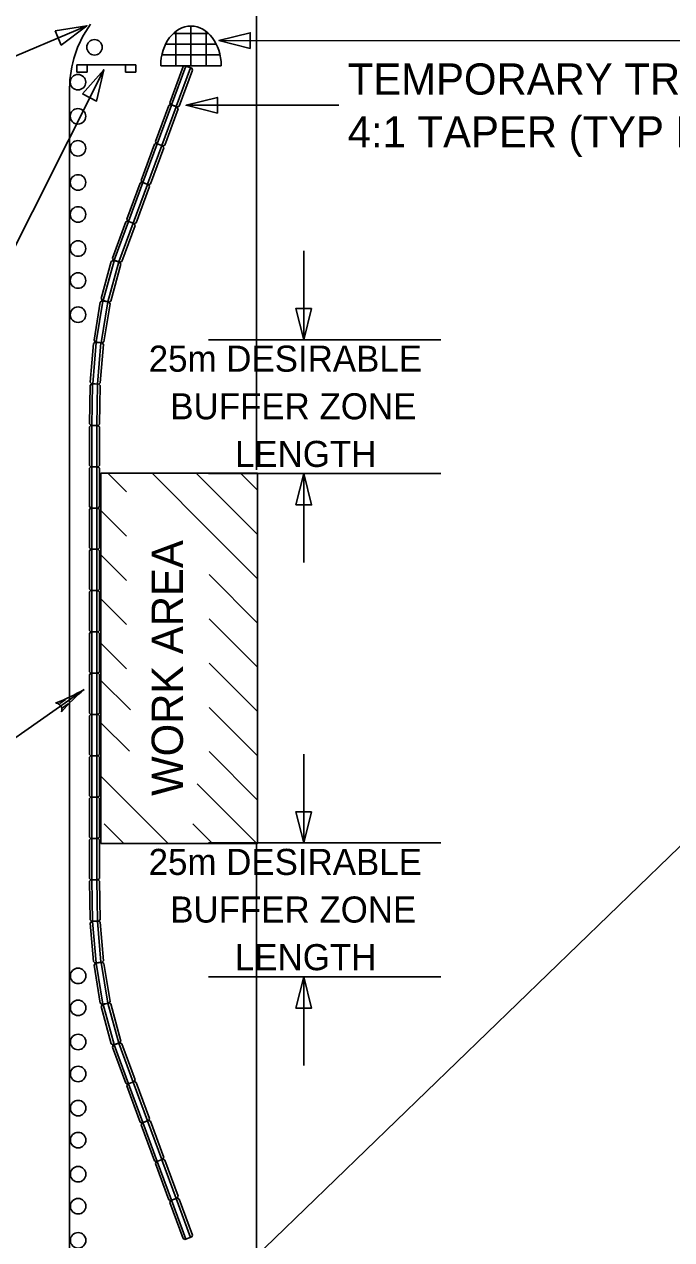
# Model space of a CAD drawing. Extents: x 2179 to 2395, y 134 to 413.
# Drawn here: x 2223.4 to 2253.5, y 308.2 to 364.6 of the extents above; entities that cross this region are included whole.
import ezdxf

# ---------------------------------------------------------------- set-up
doc = ezdxf.new("R2010")
doc.units = 0
for name, color, linetype in [('Level 10', 7, 'Continuous'), ('Level 4', 7, 'Continuous'), ('Level 44', 7, 'Continuous'), ('Level 5', 7, 'Continuous')]:
    doc.layers.add(name, color=color, linetype=linetype)

# ---------------------------------------------------------------- blocks, each defined once
blk = doc.blocks.new('OLDARO')
at = {"layer": 'Level 5'}
for p, q in [((-2.01, 0.25), (-2.69, 0.25)), ((-2.05, -0.25), (-2.73, -0.25))]:
    blk.add_line(p, q, dxfattribs=at)
for centre, radius, start, end in [((-3.37, 0), 0.626, 306.6131, 53.1011), ((1.47, 17.94), 18, 255.6368, 265.3145), ((1.31, -17.1), 17.15, 94.3866, 104.5536)]:
    blk.add_arc(centre, radius, start, end, dxfattribs=at)

msp = doc.modelspace()

# ---------------------------------------------------------------- linework, layer by layer
at = {"layer": 'Level 10'}
for p, q in [((2234.191, 343.931), (2234.191, 399.312)), ((2214.353, 359.476), (2226.333, 364.537)), ((2232.456, 363.851), (2259.582, 363.833)), ((2225.866, 362.728), (2228.601, 362.728)), ((2225.866, 362.728), (2225.866, 362.389)), ((2226.35, 362.728), (2226.35, 362.389)), ((2228.118, 362.728), (2228.118, 362.389)), ((2228.601, 362.728), (2228.601, 362.388)), ((2227.115, 362.499), (2213.674, 335.743)), ((2225.866, 362.389), (2226.35, 362.389)), ((2228.118, 362.388), (2228.601, 362.388)), ((2230.93, 360.851), (2238.022, 360.851)), ((2236.39, 349.972), (2236.39, 354.088)), ((2231.974, 349.972), (2242.752, 349.972)), ((2226.983, 326.608), (2226.983, 343.778)), ((2234.248, 343.778), (2226.983, 343.778)), ((2228.165, 342.912), (2227.299, 343.778)), ((2232.112, 341.018), (2229.352, 343.778)), ((2232.033, 343.149), (2231.404, 343.778)), ((2231.974, 343.759), (2242.752, 343.759)), ((2234.248, 342.988), (2233.458, 343.778)), ((2234.248, 326.608), (2234.248, 343.778)), ((2236.39, 339.644), (2236.39, 343.759)), ((2234.248, 340.935), (2232.003, 343.18)), ((2228.165, 340.86), (2226.989, 342.036)), ((2234.248, 338.882), (2232.003, 341.127)), ((2228.165, 338.807), (2226.989, 339.983)), ((2234.248, 336.83), (2232.003, 339.075)), ((2228.165, 336.754), (2226.989, 337.93)), ((2234.248, 334.777), (2232.003, 337.022)), ((2228.165, 334.701), (2226.989, 335.877)), ((2234.248, 332.725), (2232.003, 334.969)), ((2228.35, 332.8), (2226.949, 334.201)), ((2213.934, 325.161), (2226.209, 333.747)), ((2234.248, 330.672), (2232.003, 332.916)), ((2228.302, 330.884), (2226.983, 332.203)), ((2234.248, 328.619), (2232.003, 330.864)), ((2236.385, 326.627), (2236.385, 330.742)), ((2230.101, 326.608), (2226.983, 329.726)), ((2234.248, 326.567), (2231.447, 329.368)), ((2231.006, 304.399), (2256.495, 329.053)), ((2228.048, 326.608), (2227.138, 327.519)), ((2232.154, 326.608), (2231.241, 327.521)), ((2234.248, 326.608), (2226.983, 326.608)), ((2231.97, 326.627), (2242.747, 326.627)), ((2234.191, 178.244), (2234.191, 326.608)), ((2231.97, 320.414), (2242.747, 320.414)), ((2236.385, 316.298), (2236.385, 320.414)), ((2225.531, 313.635), (2225.531, 306.457))]:
    msp.add_line(p, q, dxfattribs=at)
for points in [[(2233.907, 363.487), (2232.456, 363.851), (2233.907, 364.212)], [(2226.133, 361.371), (2227.115, 362.499), (2226.78, 361.042)], [(2232.381, 360.488), (2230.93, 360.851), (2232.381, 361.213)], [(2236.022, 318.963), (2236.385, 320.414), (2236.748, 318.963)]]:
    msp.add_lwpolyline(points, close=True, dxfattribs=at)
for centre in [(2226.683, 363.538), (2225.918, 361.918), (2225.918, 360.335), (2225.918, 358.851), (2225.919, 357.268), (2225.919, 355.784), (2225.919, 354.2), (2225.919, 352.716), (2225.919, 351.133), (2225.923, 320.461), (2225.923, 318.977), (2225.923, 317.394), (2225.923, 315.91), (2225.924, 314.327), (2225.924, 312.843), (2225.924, 311.26), (2225.924, 309.776), (2225.924, 308.193)]:
    msp.add_circle(centre, 0.359, dxfattribs=at)
at = {"layer": 'Level 4'}
for p, q in [((2230.456, 362.683), (2230.456, 364.278)), ((2231.156, 362.683), (2231.156, 364.525)), ((2231.856, 362.683), (2231.856, 364.278)), ((2229.98, 363.683), (2232.333, 363.683)), ((2230.343, 364.183), (2231.969, 364.183)), ((2229.807, 363.183), (2232.506, 363.183)), ((2229.753, 362.683), (2232.56, 362.683)), ((2230.796, 362.643), (2230.176, 360.966)), ((2230.262, 360.865), (2230.927, 362.664)), ((2230.478, 360.786), (2231.142, 362.585)), ((2230.881, 362.681), (2230.796, 362.643)), ((2231.191, 362.567), (2230.881, 362.681)), ((2231.23, 362.483), (2231.191, 362.567)), ((2230.61, 360.806), (2231.23, 362.483)), ((2229.592, 359.061), (2230.257, 360.86)), ((2230.211, 360.878), (2230.126, 360.839)), ((2230.176, 360.966), (2230.215, 360.882)), ((2230.521, 360.763), (2230.211, 360.878)), ((2230.215, 360.882), (2230.526, 360.768)), ((2230.126, 360.839), (2229.506, 359.162)), ((2229.808, 358.982), (2230.472, 360.782)), ((2229.941, 359.003), (2230.56, 360.679)), ((2230.56, 360.679), (2230.521, 360.763)), ((2230.61, 360.806), (2230.526, 360.768)), ((2229.506, 359.162), (2229.546, 359.078)), ((2229.463, 359.038), (2228.843, 357.361)), ((2228.929, 357.26), (2229.594, 359.059)), ((2229.144, 357.181), (2229.809, 358.981)), ((2229.277, 357.202), (2229.896, 358.878)), ((2229.548, 359.077), (2229.463, 359.038)), ((2229.546, 359.078), (2229.856, 358.964)), ((2229.858, 358.962), (2229.548, 359.077)), ((2229.941, 359.003), (2229.856, 358.964)), ((2229.896, 358.878), (2229.858, 358.962)), ((2228.802, 357.237), (2228.182, 355.56)), ((2228.268, 355.459), (2228.933, 357.258)), ((2228.484, 355.38), (2229.148, 357.18)), ((2228.617, 355.401), (2229.236, 357.077)), ((2228.888, 357.276), (2228.802, 357.237)), ((2228.843, 357.361), (2228.882, 357.277)), ((2228.882, 357.277), (2229.193, 357.163)), ((2229.197, 357.161), (2228.888, 357.276)), ((2229.277, 357.202), (2229.193, 357.163)), ((2229.236, 357.077), (2229.197, 357.161)), ((2228.135, 355.438), (2227.515, 353.761)), ((2227.601, 353.66), (2228.266, 355.459)), ((2227.816, 353.581), (2228.481, 355.381)), ((2227.949, 353.602), (2228.569, 355.278)), ((2228.22, 355.477), (2228.135, 355.438)), ((2228.182, 355.56), (2228.222, 355.477)), ((2228.53, 355.362), (2228.22, 355.477)), ((2228.222, 355.477), (2228.532, 355.362)), ((2228.569, 355.278), (2228.53, 355.362)), ((2228.617, 355.401), (2228.532, 355.362)), ((2227.463, 353.604), (2226.993, 351.879)), ((2227.087, 351.786), (2227.592, 353.637)), ((2227.309, 351.726), (2227.813, 353.578)), ((2227.545, 353.65), (2227.463, 353.604)), ((2227.515, 353.761), (2227.554, 353.678)), ((2227.864, 353.563), (2227.545, 353.65)), ((2227.554, 353.678), (2227.865, 353.563)), ((2227.909, 353.483), (2227.864, 353.563)), ((2227.949, 353.602), (2227.865, 353.563)), ((2227.44, 351.759), (2227.909, 353.483)), ((2226.993, 351.879), (2227.04, 351.799)), ((2226.954, 351.715), (2226.662, 349.952)), ((2226.766, 349.868), (2227.078, 351.761)), ((2227.03, 351.769), (2226.954, 351.715)), ((2226.992, 349.831), (2227.305, 351.725)), ((2227.356, 351.715), (2227.03, 351.769)), ((2227.04, 351.799), (2227.359, 351.713)), ((2227.119, 349.877), (2227.41, 351.64)), ((2227.41, 351.64), (2227.356, 351.715)), ((2227.44, 351.759), (2227.359, 351.713)), ((2226.635, 349.789), (2226.49, 348.007)), ((2226.599, 347.933), (2226.756, 349.844)), ((2226.707, 349.849), (2226.635, 349.789)), ((2226.662, 349.952), (2226.717, 349.877)), ((2227.037, 349.821), (2226.707, 349.849)), ((2226.717, 349.877), (2227.044, 349.823)), ((2226.828, 347.913), (2226.985, 349.826)), ((2226.951, 347.969), (2227.096, 349.751)), ((2227.096, 349.751), (2227.037, 349.821)), ((2227.119, 349.877), (2227.044, 349.823)), ((2226.549, 347.918), (2226.483, 347.854)), ((2226.49, 348.007), (2226.549, 347.937)), ((2226.549, 347.937), (2226.879, 347.91)), ((2226.88, 347.912), (2226.549, 347.918)), ((2226.567, 346), (2226.598, 347.917)), ((2226.796, 345.995), (2226.829, 347.914)), ((2226.951, 347.969), (2226.879, 347.91)), ((2226.945, 347.846), (2226.88, 347.912)), ((2226.483, 347.854), (2226.452, 346.067)), ((2226.914, 346.058), (2226.945, 347.846)), ((2226.515, 345.996), (2226.449, 345.931)), ((2226.449, 345.931), (2226.451, 344.143)), ((2226.452, 346.067), (2226.517, 346.001)), ((2226.846, 345.996), (2226.515, 345.996)), ((2226.517, 346.001), (2226.847, 345.995)), ((2226.566, 344.078), (2226.564, 345.995)), ((2226.796, 344.077), (2226.794, 345.997)), ((2226.911, 345.931), (2226.846, 345.996)), ((2226.914, 346.058), (2226.847, 345.995)), ((2226.913, 344.143), (2226.911, 345.931)), ((2226.515, 344.081), (2226.449, 344.016)), ((2226.449, 344.016), (2226.451, 342.228)), ((2226.451, 344.143), (2226.517, 344.078)), ((2226.846, 344.08), (2226.515, 344.081)), ((2226.517, 344.078), (2226.847, 344.078)), ((2226.566, 342.163), (2226.564, 344.08)), ((2226.796, 342.162), (2226.794, 344.082)), ((2226.911, 344.016), (2226.846, 344.08)), ((2226.913, 344.143), (2226.847, 344.078)), ((2226.913, 342.228), (2226.911, 344.016)), ((2226.515, 342.166), (2226.449, 342.1)), ((2226.449, 342.1), (2226.451, 340.313)), ((2226.451, 342.228), (2226.517, 342.163)), ((2226.846, 342.165), (2226.515, 342.166)), ((2226.517, 342.163), (2226.847, 342.163)), ((2226.566, 340.248), (2226.564, 342.165)), ((2226.796, 340.247), (2226.794, 342.166)), ((2226.911, 342.101), (2226.846, 342.165)), ((2226.913, 342.228), (2226.847, 342.163)), ((2226.913, 340.313), (2226.911, 342.101)), ((2226.515, 340.251), (2226.449, 340.185)), ((2226.449, 340.185), (2226.451, 338.398)), ((2226.451, 340.313), (2226.517, 340.248)), ((2226.846, 340.25), (2226.515, 340.251)), ((2226.517, 340.248), (2226.847, 340.248)), ((2226.566, 338.333), (2226.564, 340.25)), ((2226.796, 338.332), (2226.794, 340.251)), ((2226.911, 340.186), (2226.846, 340.25)), ((2226.913, 340.313), (2226.847, 340.248)), ((2226.913, 338.398), (2226.911, 340.186)), ((2226.515, 338.336), (2226.449, 338.27)), ((2226.451, 338.398), (2226.517, 338.333)), ((2226.846, 338.335), (2226.515, 338.336)), ((2226.517, 338.333), (2226.847, 338.333)), ((2226.566, 336.418), (2226.564, 338.335)), ((2226.796, 336.417), (2226.794, 338.336)), ((2226.911, 338.271), (2226.846, 338.335)), ((2226.913, 338.398), (2226.847, 338.333)), ((2226.449, 338.27), (2226.451, 336.483)), ((2226.913, 336.483), (2226.911, 338.271)), ((2226.449, 334.561), (2226.45, 336.349)), ((2226.45, 336.349), (2226.516, 336.414)), ((2226.451, 336.483), (2226.517, 336.418)), ((2226.516, 336.414), (2226.847, 336.413)), ((2226.517, 336.418), (2226.847, 336.418)), ((2226.566, 336.414), (2226.563, 334.496)), ((2226.795, 336.414), (2226.794, 334.495)), ((2226.913, 336.483), (2226.847, 336.418)), ((2226.913, 336.349), (2226.847, 336.413)), ((2226.913, 336.349), (2226.911, 334.56)), ((2226.514, 334.496), (2226.449, 334.561)), ((2226.449, 332.646), (2226.45, 334.433)), ((2226.45, 334.433), (2226.516, 334.498)), ((2226.845, 334.496), (2226.514, 334.496)), ((2226.516, 334.498), (2226.847, 334.498)), ((2226.566, 334.498), (2226.563, 332.581)), ((2226.795, 334.499), (2226.794, 332.58)), ((2226.911, 334.56), (2226.845, 334.496)), ((2226.913, 334.434), (2226.847, 334.498)), ((2226.913, 334.434), (2226.911, 332.645)), ((2226.514, 332.58), (2226.449, 332.646)), ((2226.449, 330.731), (2226.45, 332.518)), ((2226.45, 332.518), (2226.516, 332.583)), ((2226.845, 332.581), (2226.514, 332.58)), ((2226.516, 332.583), (2226.847, 332.583)), ((2226.566, 332.583), (2226.563, 330.666)), ((2226.795, 332.584), (2226.794, 330.665)), ((2226.911, 332.645), (2226.845, 332.581)), ((2226.913, 332.518), (2226.847, 332.583)), ((2226.913, 332.518), (2226.911, 330.73)), ((2226.514, 330.665), (2226.449, 330.731)), ((2226.449, 328.816), (2226.45, 330.603)), ((2226.45, 330.603), (2226.516, 330.668)), ((2226.845, 330.666), (2226.514, 330.665)), ((2226.516, 330.668), (2226.847, 330.668)), ((2226.566, 330.668), (2226.563, 328.751)), ((2226.795, 330.669), (2226.794, 328.75)), ((2226.911, 330.73), (2226.845, 330.666)), ((2226.913, 330.603), (2226.847, 330.668)), ((2226.913, 330.603), (2226.911, 328.815)), ((2226.514, 328.75), (2226.449, 328.816)), ((2226.45, 328.688), (2226.516, 328.753)), ((2226.845, 328.751), (2226.514, 328.75)), ((2226.516, 328.753), (2226.847, 328.753)), ((2226.566, 328.753), (2226.563, 326.836)), ((2226.795, 328.754), (2226.794, 326.835)), ((2226.911, 328.815), (2226.845, 328.751)), ((2226.913, 328.688), (2226.847, 328.753)), ((2226.449, 326.901), (2226.45, 328.688)), ((2226.913, 328.688), (2226.911, 326.9)), ((2226.514, 326.835), (2226.449, 326.901)), ((2226.449, 324.985), (2226.45, 326.773)), ((2226.45, 326.773), (2226.516, 326.838)), ((2226.845, 326.836), (2226.514, 326.835)), ((2226.516, 326.838), (2226.847, 326.838)), ((2226.566, 326.838), (2226.563, 324.921)), ((2226.795, 326.839), (2226.794, 324.919)), ((2226.911, 326.9), (2226.845, 326.836)), ((2226.913, 326.773), (2226.847, 326.838)), ((2226.913, 326.773), (2226.911, 324.985)), ((2226.514, 324.92), (2226.449, 324.985)), ((2226.451, 324.849), (2226.516, 324.915)), ((2226.482, 323.062), (2226.451, 324.849)), ((2226.845, 324.921), (2226.514, 324.92)), ((2226.516, 324.915), (2226.847, 324.921)), ((2226.566, 324.916), (2226.598, 322.999)), ((2226.795, 324.921), (2226.828, 323.002)), ((2226.911, 324.985), (2226.845, 324.921)), ((2226.914, 324.858), (2226.847, 324.921)), ((2226.914, 324.858), (2226.944, 323.07)), ((2226.944, 323.07), (2226.88, 323.004)), ((2226.549, 322.998), (2226.482, 323.062)), ((2226.489, 322.909), (2226.549, 322.979)), ((2226.635, 321.128), (2226.489, 322.909)), ((2226.549, 322.979), (2226.879, 323.006)), ((2226.88, 323.004), (2226.549, 322.998)), ((2226.598, 322.983), (2226.755, 321.072)), ((2226.828, 323.003), (2226.984, 321.09)), ((2226.95, 322.947), (2226.879, 323.006)), ((2226.95, 322.947), (2227.096, 321.165)), ((2226.707, 321.067), (2226.635, 321.128)), ((2226.662, 320.965), (2226.716, 321.04)), ((2226.953, 319.201), (2226.662, 320.965)), ((2227.036, 321.095), (2226.707, 321.067)), ((2226.716, 321.04), (2227.043, 321.093)), ((2226.765, 321.048), (2227.078, 319.155)), ((2226.992, 321.085), (2227.304, 319.191)), ((2227.096, 321.165), (2227.036, 321.095)), ((2227.118, 321.039), (2227.043, 321.093)), ((2227.118, 321.039), (2227.409, 319.276)), ((2227.03, 319.147), (2226.953, 319.201)), ((2227.356, 319.201), (2227.03, 319.147)), ((2227.039, 319.117), (2227.359, 319.203)), ((2227.087, 319.13), (2227.591, 317.279)), ((2227.309, 319.19), (2227.813, 317.338)), ((2227.409, 319.276), (2227.356, 319.201)), ((2227.439, 319.158), (2227.359, 319.203)), ((2227.439, 319.158), (2227.909, 317.433)), ((2226.992, 319.037), (2227.039, 319.117)), ((2227.463, 317.312), (2226.992, 319.037)), ((2227.909, 317.433), (2227.863, 317.353)), ((2227.544, 317.266), (2227.463, 317.312)), ((2227.514, 317.155), (2227.554, 317.239)), ((2228.134, 315.478), (2227.514, 317.155)), ((2227.863, 317.353), (2227.544, 317.266)), ((2227.554, 317.239), (2227.865, 317.353)), ((2227.6, 317.256), (2228.265, 315.457)), ((2227.816, 317.335), (2228.481, 315.535)), ((2227.949, 317.314), (2227.865, 317.353)), ((2227.949, 317.314), (2228.568, 315.638)), ((2228.22, 315.439), (2228.134, 315.478)), ((2228.182, 315.356), (2228.221, 315.44)), ((2228.802, 313.679), (2228.182, 315.356)), ((2228.53, 315.554), (2228.22, 315.439)), ((2228.221, 315.44), (2228.532, 315.554)), ((2228.268, 315.457), (2228.933, 313.658)), ((2228.483, 315.536), (2229.148, 313.736)), ((2228.568, 315.638), (2228.53, 315.554)), ((2228.616, 315.515), (2228.532, 315.554)), ((2228.616, 315.515), (2229.235, 313.839)), ((2228.887, 313.64), (2228.802, 313.679)), ((2228.842, 313.555), (2228.882, 313.639)), ((2229.462, 311.878), (2228.842, 313.555)), ((2228.882, 313.639), (2229.193, 313.753)), ((2229.197, 313.755), (2228.887, 313.64)), ((2228.928, 313.656), (2229.593, 311.857)), ((2229.144, 313.735), (2229.809, 311.935)), ((2229.277, 313.714), (2229.193, 313.753)), ((2229.235, 313.839), (2229.197, 313.755)), ((2229.277, 313.714), (2229.896, 312.038)), ((2229.548, 311.839), (2229.462, 311.878)), ((2229.506, 311.754), (2229.545, 311.838)), ((2229.545, 311.838), (2229.856, 311.952)), ((2229.857, 311.954), (2229.548, 311.839)), ((2229.592, 311.855), (2230.257, 310.056)), ((2229.807, 311.934), (2230.472, 310.134)), ((2229.94, 311.913), (2229.856, 311.952)), ((2229.896, 312.038), (2229.857, 311.954)), ((2229.94, 311.913), (2230.559, 310.237)), ((2230.126, 310.077), (2229.506, 311.754)), ((2230.521, 310.153), (2230.211, 310.038)), ((2230.215, 310.034), (2230.526, 310.148)), ((2230.477, 310.131), (2231.142, 308.331)), ((2230.559, 310.237), (2230.521, 310.153)), ((2230.61, 310.11), (2230.526, 310.148)), ((2230.61, 310.11), (2231.229, 308.433)), ((2230.211, 310.038), (2230.126, 310.077)), ((2230.175, 309.95), (2230.215, 310.034)), ((2230.796, 308.274), (2230.175, 309.95)), ((2230.261, 310.051), (2230.926, 308.252)), ((2231.229, 308.433), (2231.191, 308.349)), ((2230.881, 308.235), (2230.796, 308.274)), ((2231.191, 308.349), (2230.881, 308.235))]:
    msp.add_line(p, q, dxfattribs=at)
msp.add_ellipse((2231.156, 362.675), major_axis=(0, 1.85), ratio=0.758621, start_param=4.716532, end_param=7.849839, dxfattribs=at)
at = {"layer": 'Level 5'}
msp.add_line((2225.531, 313.635), (2225.531, 361.641), dxfattribs=at)
for points in [[(2224.855, 364.306), (2226.333, 364.537), (2225.138, 363.638)], [(2236.753, 351.423), (2236.39, 349.972), (2236.027, 351.423)], [(2236.027, 342.308), (2236.39, 343.759), (2236.753, 342.308)], [(2236.748, 328.078), (2236.385, 326.627), (2236.023, 328.078)]]:
    msp.add_lwpolyline(points, close=True, dxfattribs=at)
msp.add_arc((2230.531, 361.641), 5, 143.6679, 180, dxfattribs=at)

# ---------------------------------------------------------------- block references
at = {"layer": 'Level 10', "xscale": 0.4838, "yscale": 0.4838000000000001, "rotation": 34.97582831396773}
msp.add_blockref('OLDARO', (2226.209, 333.747), dxfattribs=at)

# ---------------------------------------------------------------- texts
at = {"layer": 'Level 10'}
for s, p in [('TEMPORARY TRAFFIC BARRIER ', (2238.429, 361.34)), ('4:1 TAPER (TYP BOTH ENDS)', (2238.429, 358.889))]:
    msp.add_text(s, height=1.451, dxfattribs=at).set_placement(p)
msp.add_text('WORK AREA', height=1.4514, rotation=90, dxfattribs=at).set_placement((2230.785, 328.812))
at = {"layer": 'Level 44'}
for s, p in [('25m DESIRABLE', (2229.199, 348.489)), ('BUFFER ZONE', (2230.199, 346.279)), ('LENGTH', (2233.199, 344.07)), ('25m DESIRABLE', (2229.195, 325.143)), ('BUFFER ZONE', (2230.195, 322.934)), ('LENGTH', (2233.195, 320.724))]:
    msp.add_text(s, height=1.2095, dxfattribs=at).set_placement(p)

doc.saveas('drawing.dxf')
